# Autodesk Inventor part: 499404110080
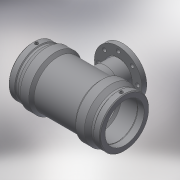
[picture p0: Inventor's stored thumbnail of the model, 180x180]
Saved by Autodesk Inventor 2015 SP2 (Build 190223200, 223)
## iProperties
Created: 2017-06
Part Number: 499404110080
Material: Generic
Description: PLASSON FLANGED TEE 110x80x110
Document SubType Name: Modeling
Designer: KIM
Mass: 57.3761 g
Surface Area: 241.06 cm^2
Volume: 57.3761 cm^3
Density: 1 g/cm^3
Appearance: Default
Author: KIM
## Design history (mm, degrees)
derived "499404.ipt"
feature "Solid1::499404.ipt"
tag "TaggingFeature1"
body "Solid1"
other parameters: "d13" = 326, "d14" = 17.6296, "d17" = 99, "d19" = 3.52592, "d20" = 168 deg, "d22" = 132.99, "d23" = 143, "d24" = 129.0003, "d25" = 135 deg, "d26" = 228.2, "d27" = 135 deg, "d29" = 81, "d35" = 15, "d39" = 5 deg, "d45" = 4, "d46" = 14, "d47" = 0, "d48" = -181, "d55" = 128.7, "d56" = 143, "d57" = 114.1, "d58" = 135 deg, "d59" = 71, "d60" = 71, "d61" = 135 deg, "d62" = 181, "d72" = 148.33, "d73" = 74.165, "d74" = -181, "d84" = 181, "d87" = 138, "d89" = 96, "d91" = 15 deg, "d92" = 104, "d95" = 4.14, "d97" = 18, "d100" = 0, "d102" = 360 deg, "d105" = 0, "d107" = 0, "d108" = 3, "d109" = 0, "d110" = 21.3, "d111" = 7.1, "L_" = 326, "L_1" = 71, "D_" = 143, "A_" = 81, "d_2" = 12, "H_" = 181, "d_1" = 138, "s_" = 18
